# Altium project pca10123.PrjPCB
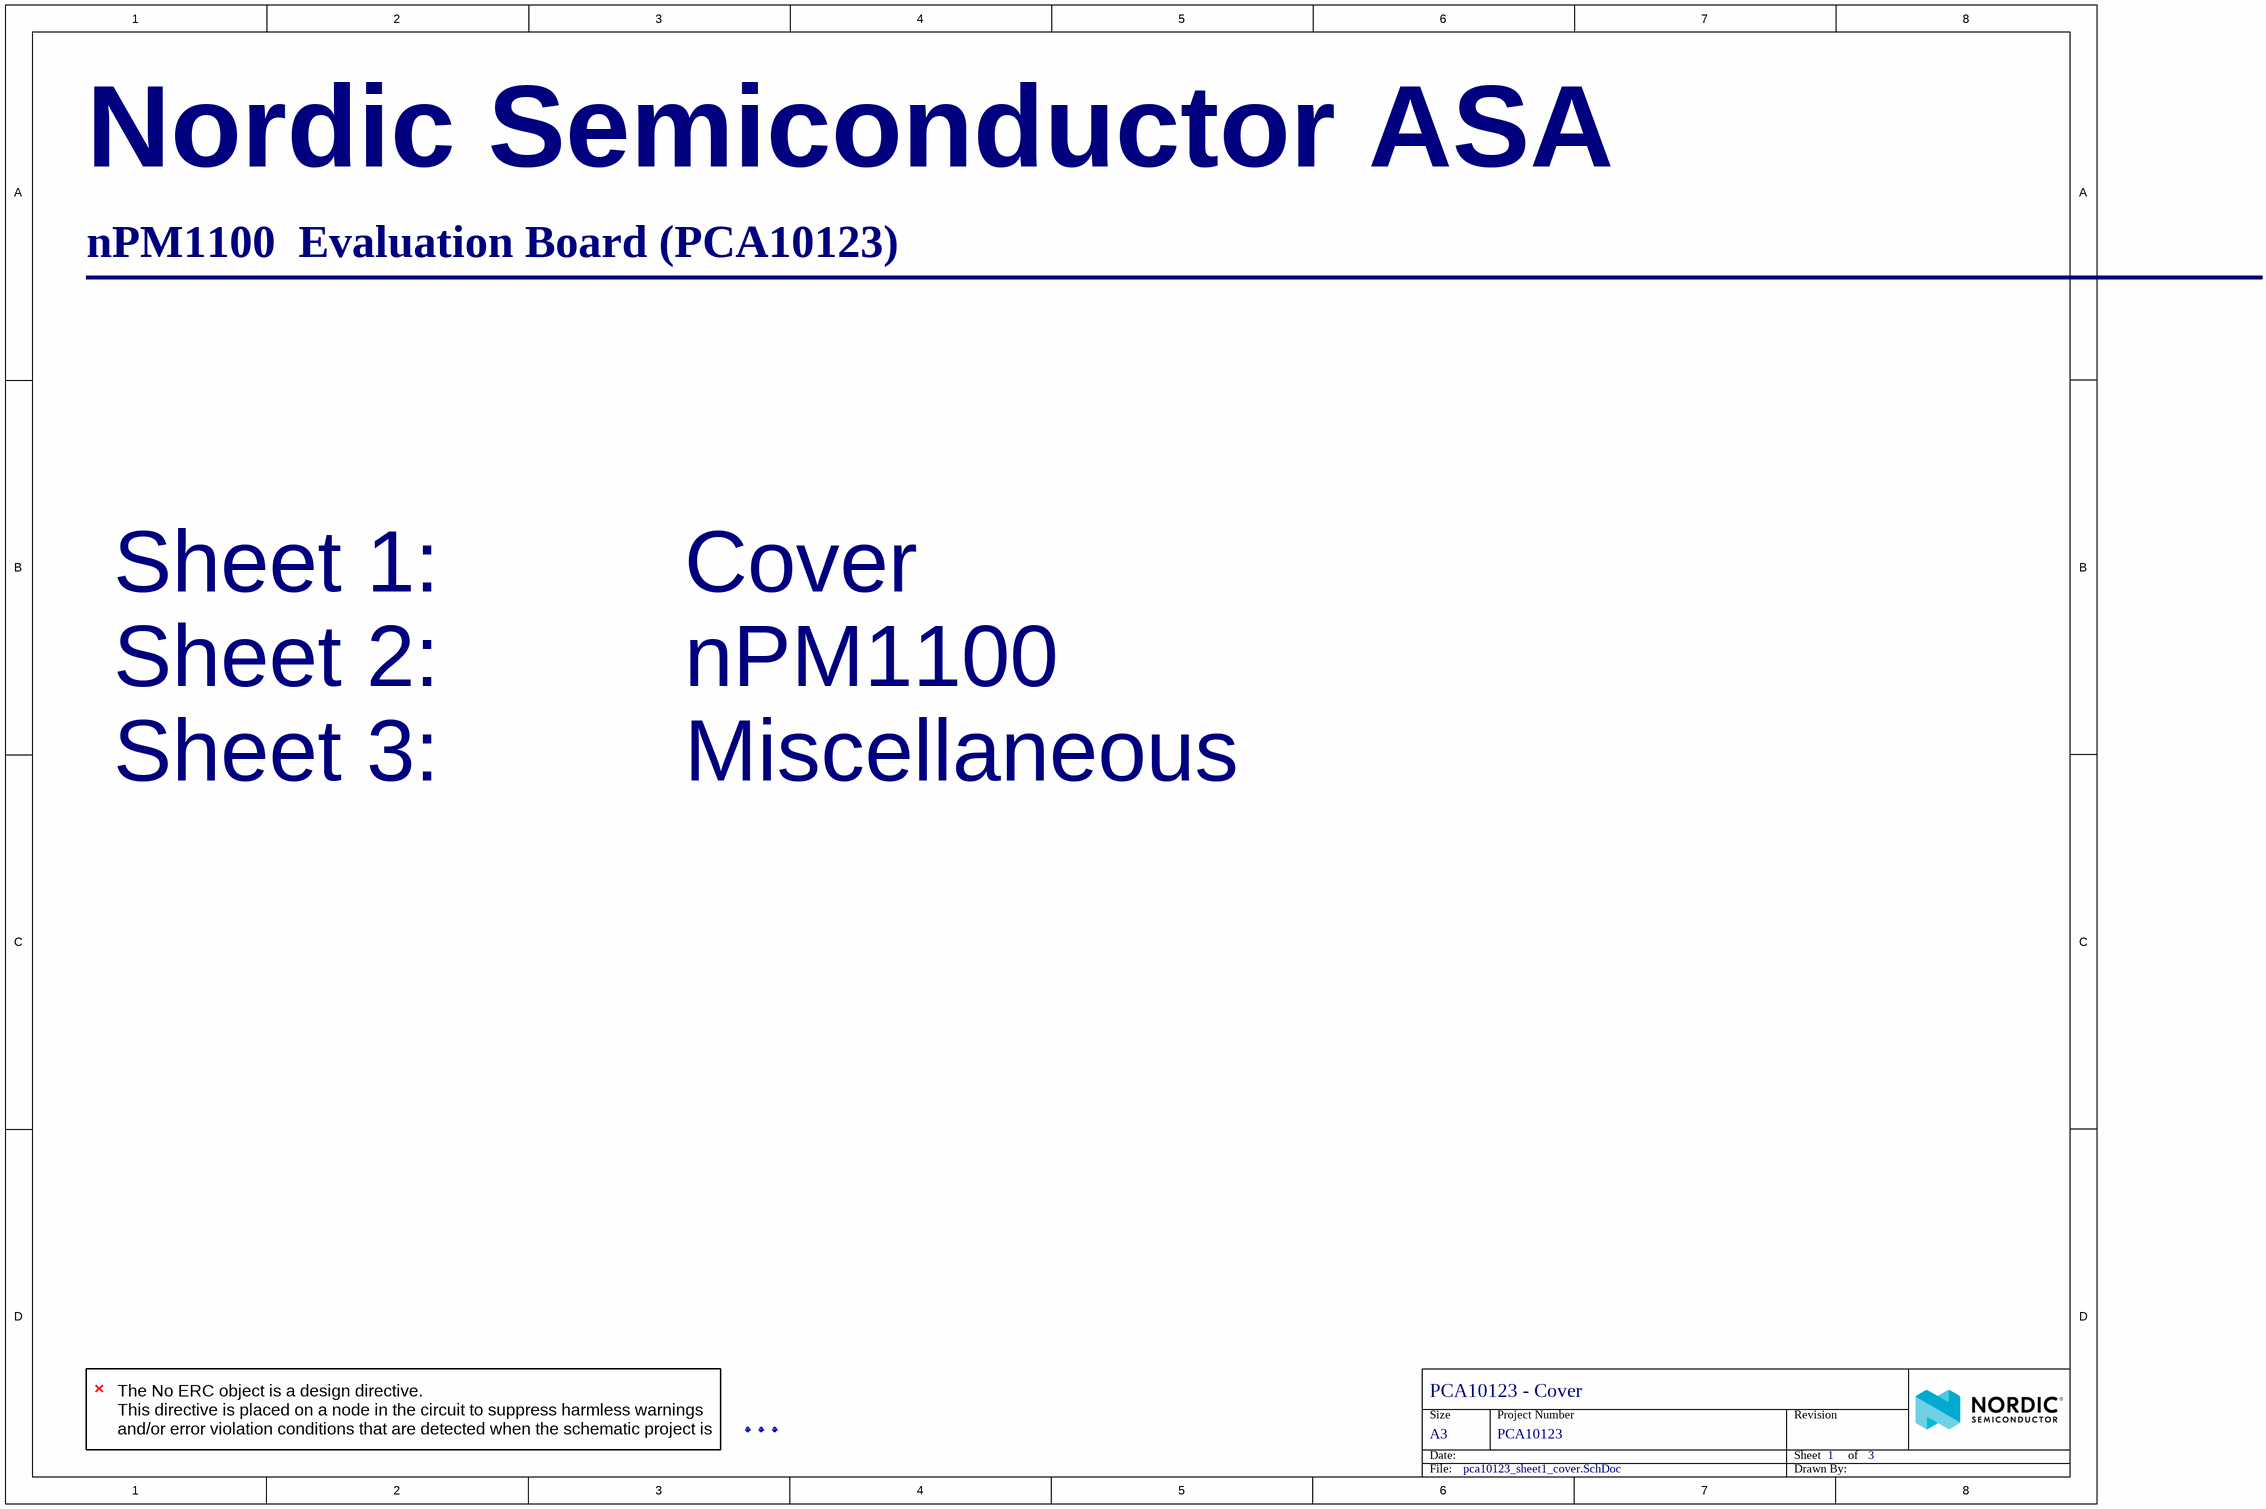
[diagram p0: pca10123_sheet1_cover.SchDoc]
Auth: GETR; BoardThickness: 1.6mm; BoardTitle: nPM1100 Evaluation kit; NrOfLayers: 4; Organization: Nordic Semiconductor; PCAName: PCA10123; PCBNumber: 400535; PCBRevision: 0154GETR; PCBStackup: 4001; ProjectName: nPM1100 Evaluation Kit; ProjectNumber: 4477; Rev: 1.0.0; SilkscreenColor: White; SoldermaskColor: Blue; SurfaceFinish: ENIG Gold
3 sheets, 80 parts. Net scope: flat (ports and power ports of the same name join across sheets).
Board file: 400535.PcbDoc
Sheets:
  pca10123_sheet1_cover.SchDoc
  pca10123-sheet2_nPM1100.SchDoc
  pca10123-sheet3_misc.SchDoc

## Sheet pca10123_sheet1_cover.SchDoc: PCA10123 - Cover
size A3; Organization: Nordic Semiconductor; DocumentNumber: 1; Revision: 1.0.0; SheetNumber: 1; SheetTotal: 3; Author: GETR; CompanyName: Nordic Semiconductor; DocumentSize: A3

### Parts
Fid1  Fiducial mark  [Fiducial]  (value not drawn)
Fid2  Fiducial mark  [Fiducial]  (value not drawn)
Fid3  Fiducial mark  [Fiducial]  (value not drawn)

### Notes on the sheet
- Nordic Semiconductor ASA
- nPM1100  Evaluation Board (PCA10123)
- ________________________________________________________________
- Sheet 1:          Cover
- Sheet 2:          nPM1100
- Sheet 3:          Miscellaneous
- The No ERC object is a design directive.
  This directive is placed on a node in the circuit to suppress harmless warnings and/or error violation conditions that are detected when the schematic project is compiled.

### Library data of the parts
Fid1-Fid3 = Fid-Mark: Manufacturer: N.A.; Value: N.A.; Pad Count: 1

## Sheet pca10123-sheet2_nPM1100.SchDoc: PCA10123 - Misc
size A4; Organization: Nordic Semiconductor; DocumentNumber: 2; Revision: 1.0.0; SheetNumber: 2; SheetTotal: 3; Author: GETR; CompanyName: Nordic Semiconductor; DocumentSize: A4; Project Number: 4477
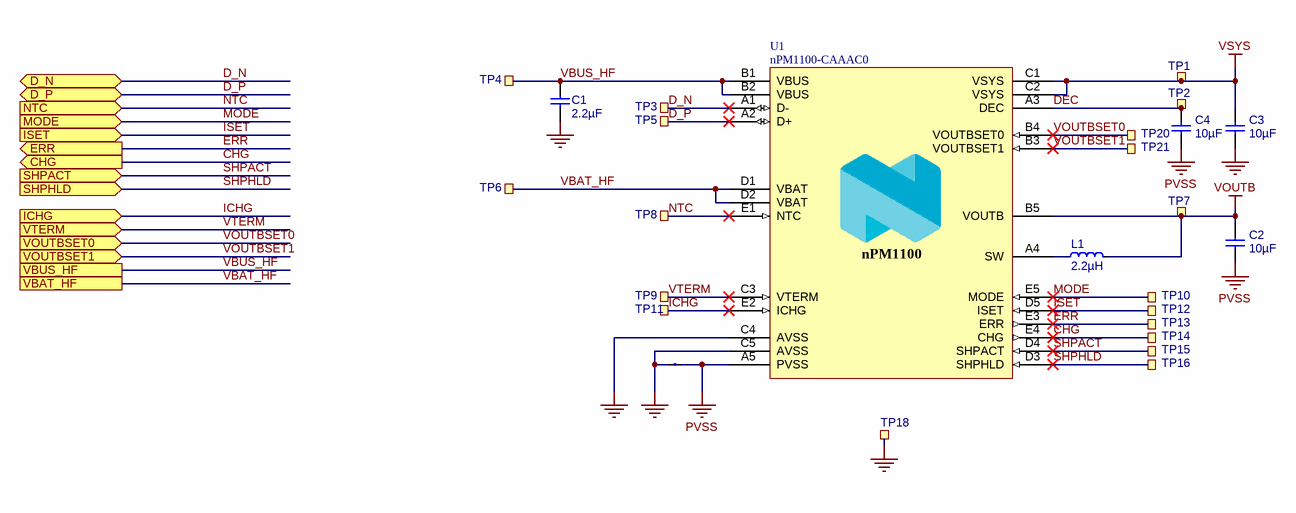
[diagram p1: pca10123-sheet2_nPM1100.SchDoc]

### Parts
C1  2.2µF  [CAPC1608X06L]
C2  10µF  [CAPC1608X06L]
C3  10µF  [CAPC1608X06L]
C4  10µF  [CAPC1608X06L]
J1  N.A.  [2 PIN STARPOINT]  (value not drawn)  (net tie, no BOM)
L1  2.2µH  [INDC2016X10N]
TP1  Ø1.5mm,SMD  [TP_SMD_D1.5mm]  (value not drawn)  (no BOM)
TP2  Ø1.5mm,SMD  [TP_SMD_D1.5mm]  (value not drawn)  (no BOM)
TP3  Ø1.5mm,SMD  [TP_SMD_D1.5mm]  (value not drawn)  (no BOM)
TP4  Ø1.5mm,SMD  [TP_SMD_D1.5mm]  (value not drawn)  (no BOM)
TP5  Ø1.5mm,SMD  [TP_SMD_D1.5mm]  (value not drawn)  (no BOM)
TP6  Ø1.5mm,SMD  [TP_SMD_D1.5mm]  (value not drawn)  (no BOM)
TP7  Ø1.5mm,SMD  [TP_SMD_D1.5mm]  (value not drawn)  (no BOM)
TP8  Ø1.5mm,SMD  [TP_SMD_D1.5mm]  (value not drawn)  (no BOM)
TP9  Ø1.5mm,SMD  [TP_SMD_D1.5mm]  (value not drawn)  (no BOM)
TP10  Ø1.5mm,SMD  [TP_SMD_D1.5mm]  (value not drawn)  (no BOM)
TP11  Ø1.5mm,SMD  [TP_SMD_D1.5mm]  (value not drawn)  (no BOM)
TP12  Ø1.5mm,SMD  [TP_SMD_D1.5mm]  (value not drawn)  (no BOM)
TP13  Ø1.5mm,SMD  [TP_SMD_D1.5mm]  (value not drawn)  (no BOM)
TP14  Ø1.5mm,SMD  [TP_SMD_D1.5mm]  (value not drawn)  (no BOM)
TP15  Ø1.5mm,SMD  [TP_SMD_D1.5mm]  (value not drawn)  (no BOM)
TP16  Ø1.5mm,SMD  [TP_SMD_D1.5mm]  (value not drawn)  (no BOM)
TP18  Ø1.5mm,SMD  [TP_SMD_D1.5mm]  (value not drawn)  (no BOM)
TP20  Ø1.5mm,SMD  [TP_SMD_D1.5mm]  (value not drawn)  (no BOM)
TP21  Ø1.5mm,SMD  [TP_SMD_D1.5mm]  (value not drawn)  (no BOM)
U1  nPM1100-CAAAC0  [BGA25C40P5X5_200X200X50]

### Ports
CHG (out), D_N (bidir), D_P (bidir), ERR (out), ICHG (in), ISET (in), MODE (in), NTC (in), SHPACT (in), SHPHLD (in), VBAT_HF, VBUS_HF, VOUTBSET0 (in), VOUTBSET1 (in), VTERM (in)

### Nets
GND: C1.1 C3.1 J1.2 TP18.1 U1.C4(AVSS) U1.C5(AVSS)
PVSS: C2.1 C4.1 J1.1 U1.A5(PVSS)
VOUTB: C2.2 L1.2 TP7.1 U1.B5(VOUTB)
VSYS: C3.2 TP1.1 U1.C1(VSYS) U1.C2(VSYS)
CHG: TP14.1 U1.E4(CHG) ; port CHG
D_N: TP3.1 U1.A1(D-) ; port D_N
D_P: TP5.1 U1.A2(D+) ; port D_P
DEC: C4.2 TP2.1 U1.A3(DEC)
ERR: TP13.1 U1.E3(ERR) ; port ERR
ICHG: TP11.1 U1.E2(ICHG) ; port ICHG
ISET: TP12.1 U1.D5(ISET) ; port ISET
MODE: TP10.1 U1.E5(MODE) ; port MODE
NTC: TP8.1 U1.E1(NTC) ; port NTC
SHPACT: TP15.1 U1.D4(SHPACT) ; port SHPACT
SHPHLD: TP16.1 U1.D3(SHPHLD) ; port SHPHLD
VBAT_HF: TP6.1 U1.D1(VBAT) U1.D2(VBAT) ; port VBAT_HF
VBUS_HF: C1.2 TP4.1 U1.B1(VBUS) U1.B2(VBUS) ; port VBUS_HF
VOUTBSET0: TP20.1 U1.B4(VOUTBSET0) ; port VOUTBSET0
VOUTBSET1: TP21.1 U1.B3(VOUTBSET1) ; port VOUTBSET1
VTERM: TP9.1 U1.C3(VTERM) ; port VTERM
NetL1_1: L1.1 U1.A4(SW)

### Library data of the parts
C1 = C0603-2µ2-25V-X5R: Capacitor, Ceramic, X5R, ±10%, 25V; Manufacturer: Murata; Manufacturer Part Number: GRM188R61E225KA12D; Pad Count: 2; Artikkelnr Noca: N.A.
C2-C4 = 0603-10u-10V-X7T-GRM188: CAP CER 10UF 10V X7T 0603; Manufacturer: Murata; Manufacturer Part Number: GRM188D71A106MA73; Part number IPS: 00000004696; Note: 10VDC; Artikkelnr Noca: N.A.; Pad Count: 2
J1 = 2 pin starpoint: Starpoint; Pad Count: 2
L1 = CIGT201610EH2R2MNE: FIXED IND 2.2UH 2.5A 87MOHM SMD; Manufacturer: Samsung Electro-Mechanics; Pad Count: 2; Note: 2.2µH Unshielded Thin Film Inductor 2.5A 87mOhm Max 0806 (2016 Metric); Artikkelnr Noca: N.A.
TP1-TP16 TP18 TP20 TP21 = TP_SMD_Ø1.5MM: 1.5mm circular SMD testpad; Manufacturer: Nordic Semiconductor; Manufacturer Part Number: N.A.; Pad Count: 1
U1 = nPM1100-CAAAC0: Li-Ion/Li-Polymer USB battery charger with a high efficiency buck regulator; Manufacturer: Nordic Semiconductor; Note: N.A.; Pad Count: 25

## Sheet pca10123-sheet3_misc.SchDoc: =BoardTitle
size A3; Organization: Nordic Semiconductor; DocumentNumber: 3; Revision: 1.0.0; SheetNumber: 3; SheetTotal: 3; Author: GETR; CompanyName: Nordic Semiconductor; DocumentSize: A3; Project Number: 4477
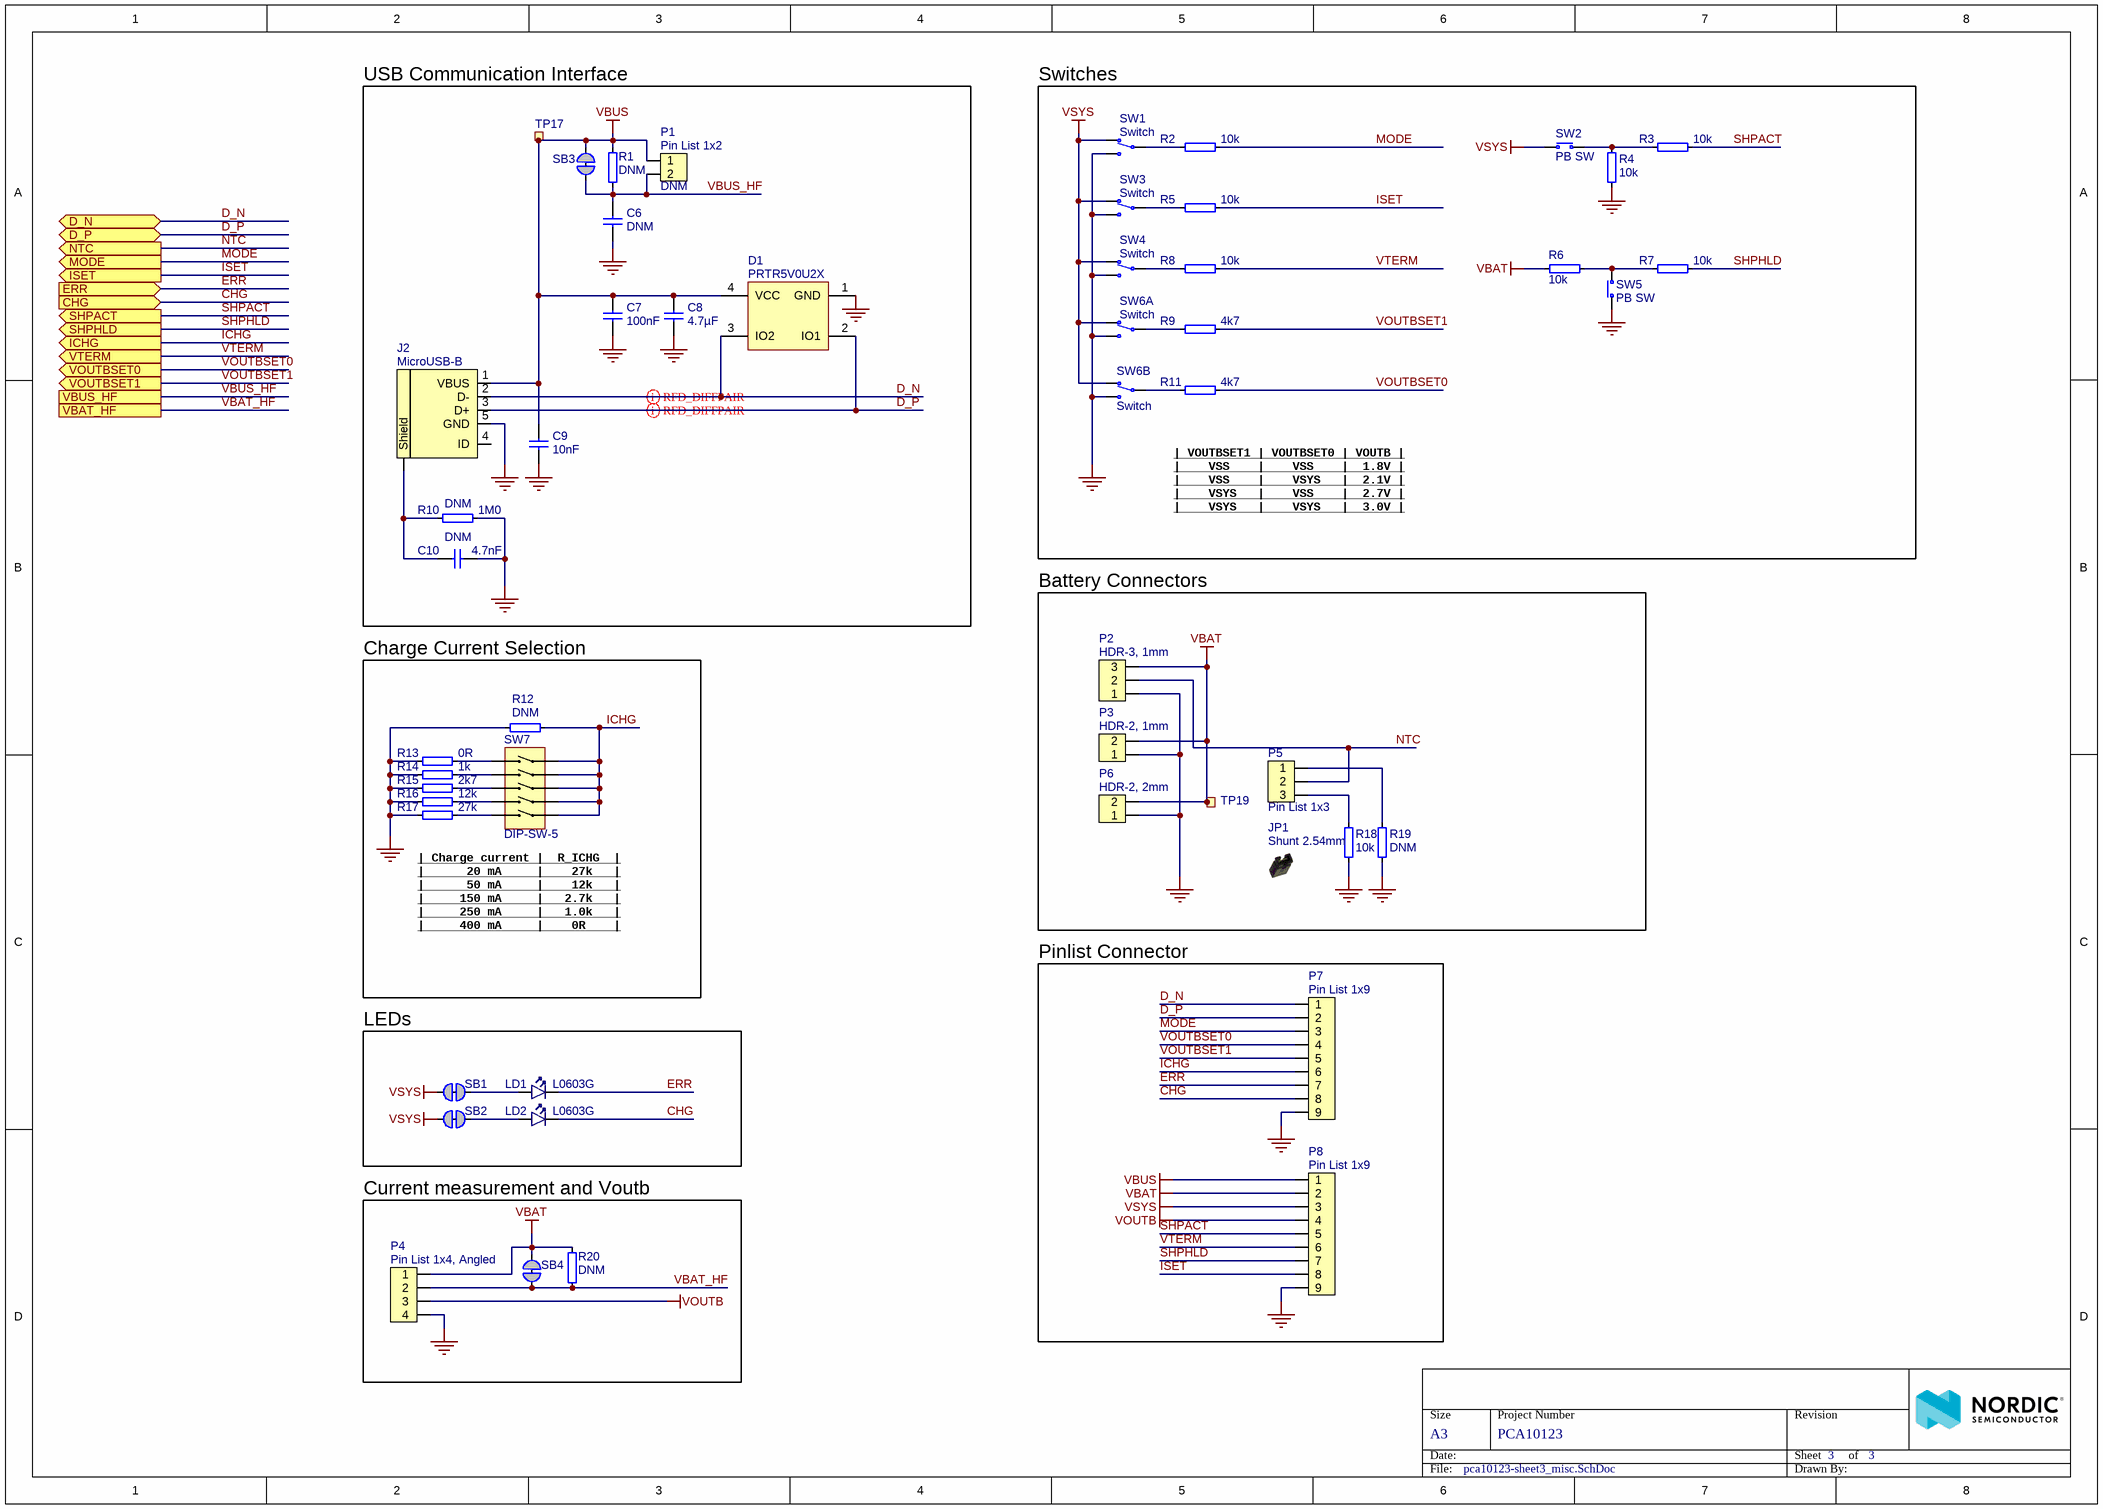
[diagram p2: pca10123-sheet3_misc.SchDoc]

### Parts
C6  DNM  [CAPC2012X11L_NC]
C7  100nF  [CAPC0603X03L_C]
C8  4.7µF  [CAPC1005X04L]
C9  10nF  [CAPC0603X03L_C]
C10  4.7nF  Assembly: DNM  [CAPC0603X03L_C]
D1  PRTR5V0U2X  [SOT190P230X110-4L]
J2  MicroUSB-B  [USB-Micro-B-RA-SMD-PiP]
JP1  Shunt 2.54mm  [Shunt_2.54mm]
LD1  L0603G  [LED_0603_R]
LD2  L0603G  [LED_0603_G]
P1  Pin List 1x2  Assembly: DNM  [LIST_1x2]
P2  HDR-3, 1mm  [SM03B-SRSS-TB]
P3  HDR-2, 1mm  [SM02B-SRSS-TB]
P4  Pin List 1x4, Angled  [LIST_ANG_1x4-SMD-2.54MM]
P5  Pin List 1x3  [LIST_1x3_SMD]
P6  HDR-2, 2mm  [S2B-PH-SM4-TB]
P7  Pin List 1x9  [LIST_1x9_SMD]
P8  Pin List 1x9  [LIST_1x9_SMD]
R1  DNM  [RESC1005X04L_NC]
R2  10k  [RESC1005X04L]
R3  10k  [RESC1005X04L]
R4  10k  [RESC1005X04L]
R5  10k  [RESC1005X04L]
R6  10k  [RESC1005X04L]
R7  10k  [RESC1005X04L]
R8  10k  [RESC1005X04L]
R9  4k7  [RESC1005X04L]
R10  1M0  Assembly: DNM  [RESC0603X03L_C]
R11  4k7  [RESC1005X04L]
R12  DNM  [RESC1005X04L_NC]
R13  0R  [RESC1005X04L]
R14  1k  [RESC1005X04L]
R15  2k7  [RESC1005X04L]
R16  12k  [RESC1005X04L]
R17  27k  [RESC1005X04L]
R18  10k  [RESC1005X04L]
R19  DNM  [RESC1608X06L_NC]
R20  DNM  [RESC1005X04L_NC]
SB1  Solderbridge  [Solderbridge_Shorted]  (value not drawn)  (net tie, no BOM)
SB2  Solderbridge  [Solderbridge_Shorted]  (value not drawn)  (net tie, no BOM)
SB3  Solderbridge  [Solderbridge_Shorted_Power]  (value not drawn)  (net tie, no BOM)
SB4  Solderbridge  [Solderbridge_Shorted_Power]  (value not drawn)  (net tie, no BOM)
SW1  Switch  [CJS-120xA]
SW2  PB SW  [C&K_PTS810]
SW3  Switch  [CJS-120xA]
SW4  Switch  [CJS-120xA]
SW5  PB SW  [C&K_PTS810]
SW6  Switch  [CAS-D20A]  (parts A,B of 2)
SW7  DIP-SW-5  [SOIC127P840X265-10N]
TP17  Ø1.5mm,SMD  [TP_SMD_D1.5mm]  (value not drawn)  (no BOM)
TP19  Ø1.5mm,SMD  [TP_SMD_D1.5mm]  (value not drawn)  (no BOM)

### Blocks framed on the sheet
USB Communication Interface: C6-C10 D1 J2 P1 R1 R10 SB3 TP17
Switches: R2-R9 R11 SW1-SW6
Battery Connectors: JP1 P2 P3 P5 P6 R18 R19 TP19
Charge Current Selection: R12-R17 SW7
Pinlist Connector: P7 P8
LEDs: LD1 LD2 SB1 SB2
Current measurement and Voutb: P4 R20 SB4

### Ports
CHG (in), D_N (bidir), D_P (bidir), ERR (in), ICHG (out), ISET (out), MODE (out), NTC (out), SHPACT (out), SHPHLD (out), VBAT_HF, VBUS_HF, VOUTBSET0 (out), VOUTBSET1 (out), VTERM (out)

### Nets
GND: C6.1 C7.2 C8.2 C9.2 C10.2 D1.1(GND) J2.5(GND) P2.1 P3.1 P4.4 P6.1 P7.9 P8.9 R4.2 R10.2 R12.1 R13.1 R14.1 R15.1 R16.1 R17.1 R18.1 R19.1 SW1.3(N.O) SW3.3(N.O) SW4.3(N.O) SW5.2(COM) SW6.1(N.O) SW6.4(N.O)
VBAT: P2.3 P3.2 P4.1 P6.2 P8.2 R6.2 R20.2 SB4.2 TP19.1
VBUS: C7.1 C8.1 C9.1 D1.4(VCC) J2.1(VBUS) P1.1 P8.1 R1.2 SB3.1 TP17.1
VOUTB: P4.3 P8.4
VSYS: P8.3 SB1.1 SB2.1 SW1.1(N.C) SW2.2(COM) SW3.1(N.C) SW4.1(N.C) SW6.3(N.C) SW6.6(N.C)
CHG: LD2.1(C) P7.8 ; port CHG
D_N: D1.3(IO2) J2.2(D-) P7.1 ; port D_N
D_P: D1.2(IO1) J2.3(D+) P7.2 ; port D_P
ERR: LD1.1(C) P7.7 ; port ERR
ICHG: P7.6 R12.2 SW7.6 SW7.7 SW7.8 SW7.9 SW7.10 ; port ICHG
ISET: P8.8 R5.2 ; port ISET
MODE: P7.3 R2.2 ; port MODE
NTC: P2.2 P5.2 ; port NTC
SHPACT: P8.5 R3.2 ; port SHPACT
SHPHLD: P8.7 R7.2 ; port SHPHLD
VBAT_HF: P4.2 R20.1 SB4.1 ; port VBAT_HF
VBUS_HF: C6.2 P1.2 R1.1 SB3.2 ; port VBUS_HF
VOUTBSET0: P7.4 R11.2 ; port VOUTBSET0
VOUTBSET1: P7.5 R9.2 ; port VOUTBSET1
VTERM: P8.6 R8.2 ; port VTERM
NetC10_1: C10.1 J2.6(Shield) R10.1
NetLD1_2: LD1.2(A) SB1.2
NetLD2_2: LD2.2(A) SB2.2
NetP5_1: P5.1 R19.2
NetP5_3: P5.3 R18.2
NetR2_1: R2.1 SW1.2(COM)
NetR3_1: R3.1 R4.1 SW2.1(N.O)
NetR5_1: R5.1 SW3.2(COM)
NetR6_1: R6.1 R7.1 SW5.1(N.O)
NetR8_1: R8.1 SW4.2(COM)
NetR9_1: R9.1 SW6.2(COM)
NetR11_1: R11.1 SW6.5(COM)
NetR13_2: R13.2 SW7.1
NetR14_2: R14.2 SW7.2
NetR15_2: R15.2 SW7.3
NetR16_2: R16.2 SW7.4
NetR17_2: R17.2 SW7.5

Not connected (* = marked no-connect by the designer): J2 4(ID)

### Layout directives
differential pair; differential pair class USB2: D_N, D_P

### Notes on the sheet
- | VOUTBSET1 | VOUTBSET0 | VOUTB |
  |    VSS    |    VSS    |  1.8V |
  |    VSS    |    VSYS   |  2.1V |
  |    VSYS   |    VSS    |  2.7V |
  |    VSYS   |    VSYS   |  3.0V |
- | Charge current |  R_ICHG  |
  |      20 mA     |    27k   |
  |      50 mA     |    12k   |
  |     150 mA     |   2.7k   |
  |     250 mA     |   1.0k   |
  |     400 mA     |    0R    |

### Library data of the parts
C6 = C0805-N.C.: Not mounted; Manufacturer: N.A.; Assembly: Not mounted; Note: Chip Cap; Pad Count: 2
C7 = C0201-100n: Capacitor, X5R, ±10%; Manufacturer: N.A.; Part number IPS: 00000001248, 00000002505; Note: 16V; Pad Count: 2
C8 = C0402-4µ7: Capacitor, X5R, ±20%; Manufacturer: N.A.; Part number IPS: 00000001251, 00000007165; Note: 10V; Artikkelnr Noca: 20039482; Pad Count: 2
C9 = C0201-10n: Capacitor, X7R, ±10%; Manufacturer: N.A.; Part number IPS: 00000003480; Note: 10V; Pad Count: 2
C10 = C0201-4n7: Chip Cap 0201 4.7nF 10% 10V X7R; Manufacturer: N.A.; Part number IPS: 00000001243; Note: Chip Cap 1%; Pad Count: 2
D1 = PRTR5V0U2X: Ultra low capacitance double rail-to-rail ESD protection diode; Manufacturer: NXP Semiconductors; Part number IPS: 00000009951; Note: N.A.; Artikkelnr Noca: 10069015; Pad Count: 4
J2 = USB-Micro-B-RA-SMD-PiP: MicroUSB-B-SMT; Manufacturer: Allen Creations Corp.; Manufacturer Part Number: AJU55-BS2111-L; Part number IPS: 00000007790; Note: N.A.; Artikkelnr Noca: 55029020; Pad Count: 5
JP1 = SHUNT JUMPER 2.54mm BLACK GOLD: SHUNT JUMPER .1" BLACK GOLD; Manufacturer: 3M; Manufacturer Part Number: 969102-0000-DA; Part number IPS: N.A.; Note: SHUNT JUMPER .1" BLACK GOLD, h=6.00mm, w=5.00mm; Artikkelnr Noca: 56099001; Pad Count: 2
LD1 = ASMT-RR45-AQ902: LED, Red, 0603, Vf=2V, - 40 to +100°C; Manufacturer: Avago; Note: 90 mcd @ 20 mA; Artikkelnr Noca: N.A.; Pad Count: 2
LD2 = ASMT-RF45-AN002: LED, Yellow Green, 0603, Vf=2V, - 40 to +100°C; Manufacturer: Avago; Note: 28 mcd @ 20 mA; Artikkelnr Noca: N.A.; Pad Count: 2
P1 = Pin List 1x2: Pin List 1x2, 2.54mm (100mil); Manufacturer: N.A.; Pad Count: 2; Artikkelnr Noca: 56019040
P2 = SM03B-SRSS-TB: 1.0mm pitch connector side entry SMD; Manufacturer: JST Sales America Inc.; Manufacturer Part Number: SM03B-SRSS-TB(LF)(SN); Part number IPS: 00000001785; Note: JST, Header; Artikkelnr Noca: N.A.; Pad Count: 3
P3 = SM02B-SRSS-TB: 1.0mm pitch connector side entry SMD; Manufacturer: JST Sales America Inc.; Manufacturer Part Number: SM02B-SRSS-TB(LF)(SN); Part number IPS: 00000007791; Part number Norautron: N.A.; Note: JST, Header; Artikkelnr Noca: 55010030; Pad Count: 2
P4 = Pin List Ang 1x4 SMD, 2.54mm: Pin List 1x4, 2.54mm (100mil), Right Angled, SMD; Manufacturer: W-CON; Manufacturer Part Number: 1125B-1104S0Z135CR02; Part number IPS: 00000004780; Pad Count: 4; Note: N.A.
P5 = Pin List 1x3 SMD: Pin List 1x3, 2.54mm (100mil), SMD; Manufacturer: W-CON; Manufacturer Part Number: 1125-1103S3M116CR02; Note: N.A.; Pad Count: 3
P6 = S2B-PH-SM4-TB: 2.0mm pitch connector side entry SMD; Manufacturer: JST Sales America Inc.; Manufacturer Part Number: S2B-PH-SM4-TB(LF)(SN); Note: JST, Header; Artikkelnr Noca: N.A.; Pad Count: 2
P7 P8 = Pin List 1x9 SMD: Pin List 1x9, 2.54mm (100mil), SMD; Manufacturer: W-CON; Manufacturer Part Number: 1125-1109S0M116R2; Note: N.A.; Artikkelnr Noca: 55010024; Pad Count: 9
R1 R12 R20 = R0402-N.C.: Not mounted; Manufacturer: N.A.; Assembly: Not mounted; Note: Chip Res; Pad Count: 2
R2-R8 R18 = R0402-10k: Resistor, ±1%, 0.063W; Manufacturer: N.A.; Part number IPS: 00000002093; Note: Chip Res 1%; Artikkelnr Noca: 27049097; Pad Count: 2
R9 R11 = R0402-4K7: Resistor, ±1%, 0.063W; Manufacturer: N.A.; Part number IPS: 00000003433; Note: Chip Res 1%; Artikkelnr Noca: 27049089; Pad Count: 2
R10 = R0201-1M0: Resistor, ±1%, 0.05W; Manufacturer: N.A.; Part number IPS: 00000001418; Note: Chip Res 1%; Pad Count: 2
R13 = R0402-0R: Resistor, ±5%, 0.063W; Manufacturer: N.A.; Part number IPS: 00000007128; Note: Chip Res 5%; Artikkelnr Noca: 27049000; Pad Count: 2
R14 = R0402-1k0: Resistor, ±1%, 0.063W; Manufacturer: N.A.; Part number IPS: 00000002218; Note: Chip Res 1%; Artikkelnr Noca: 27049073; Pad Count: 2
R15 = R0402-2k7: Resistor, ±1%, 0.063W; Manufacturer: N.A.; Note: Chip Res 1%; Artikkelnr Noca: 27049083; Pad Count: 2
R16 = R0402-12k: Resistor, ±1%, 0.063W; Manufacturer: N.A.; Note: Chip Res 1%; Artikkelnr Noca: 27049099; Pad Count: 2
R17 = R0402-27k: Resistor, ±1%, 0.063W; Manufacturer: N.A.; Part number IPS: 00000004188; Note: Chip Res 1%; Artikkelnr Noca: 27049107; Pad Count: 2
R19 = R0603-N.C.: Not mounted; Manufacturer: N.A.; Assembly: Not mounted; Note: Chip Res; Pad Count: 2
SB1 SB2 = Solderbridge Shorted: Shorted Solderbridge; Manufacturer: N.A.; Pad Count: 2
SB3 SB4 = Solderbridge Shorted Power: Shorted Solderbridge Power; Manufacturer: N.A.; Pad Count: 2
SW1 SW3 SW4 = CJS-1200TA: SMD slide Switch (ON-ON); Manufacturer: Copal Electronics Inc; Part number IPS: 00000009982; Note: N.A.; Artikkelnr Noca: 50019068; Pad Count: 3
SW2 SW5 = PTS810 SJK 250 SMTR LFS: Tactile Switch, SPNO, SMD, 260gf, 4.2x3.2x2.5mm; Manufacturer: C&K; Part number IPS: 00000001259; Note: N.A.; Pad Count: 4
SW6 = CAS-D20TA: SMD slide Switch 2xSPDT; Manufacturer: Copal Electronics Inc; Note: N.A.; Pad Count: 6
SW7 = DIP-SW5-SPST: SWITCH SLIDE DIP SPST 25MA 24V; Manufacturer: Wurth Elektronik; Manufacturer Part Number: 416131160805; Note: N.A.; Pad Count: 10
TP17 TP19 = TP_SMD_Ø1.5MM: as TP1 on sheet pca10123-sheet2_nPM1100

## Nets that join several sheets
GND: pca10123-sheet2_nPM1100 (6 pins), pca10123-sheet3_misc (29 pins)
VOUTB: pca10123-sheet2_nPM1100 (C2.2 L1.2 TP7.1 U1.B5), pca10123-sheet3_misc (P4.3 P8.4)
VSYS: pca10123-sheet2_nPM1100 (C3.2 TP1.1 U1.C1 U1.C2), pca10123-sheet3_misc (9 pins)
CHG: pca10123-sheet2_nPM1100 (TP14.1 U1.E4), pca10123-sheet3_misc (LD2.1 P7.8)
D_N: pca10123-sheet2_nPM1100 (TP3.1 U1.A1), pca10123-sheet3_misc (D1.3 J2.2 P7.1)
D_P: pca10123-sheet2_nPM1100 (TP5.1 U1.A2), pca10123-sheet3_misc (D1.2 J2.3 P7.2)
ERR: pca10123-sheet2_nPM1100 (TP13.1 U1.E3), pca10123-sheet3_misc (LD1.1 P7.7)
ICHG: pca10123-sheet2_nPM1100 (TP11.1 U1.E2), pca10123-sheet3_misc (7 pins)
ISET: pca10123-sheet2_nPM1100 (TP12.1 U1.D5), pca10123-sheet3_misc (P8.8 R5.2)
MODE: pca10123-sheet2_nPM1100 (TP10.1 U1.E5), pca10123-sheet3_misc (P7.3 R2.2)
NTC: pca10123-sheet2_nPM1100 (TP8.1 U1.E1), pca10123-sheet3_misc (P2.2 P5.2)
SHPACT: pca10123-sheet2_nPM1100 (TP15.1 U1.D4), pca10123-sheet3_misc (P8.5 R3.2)
SHPHLD: pca10123-sheet2_nPM1100 (TP16.1 U1.D3), pca10123-sheet3_misc (P8.7 R7.2)
VBAT_HF: pca10123-sheet2_nPM1100 (TP6.1 U1.D1 U1.D2), pca10123-sheet3_misc (P4.2 R20.1 SB4.1)
VBUS_HF: pca10123-sheet2_nPM1100 (C1.2 TP4.1 U1.B1 U1.B2), pca10123-sheet3_misc (C6.2 P1.2 R1.1 SB3.2)
VOUTBSET0: pca10123-sheet2_nPM1100 (TP20.1 U1.B4), pca10123-sheet3_misc (P7.4 R11.2)
VOUTBSET1: pca10123-sheet2_nPM1100 (TP21.1 U1.B3), pca10123-sheet3_misc (P7.5 R9.2)
VTERM: pca10123-sheet2_nPM1100 (TP9.1 U1.C3), pca10123-sheet3_misc (P8.6 R8.2)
